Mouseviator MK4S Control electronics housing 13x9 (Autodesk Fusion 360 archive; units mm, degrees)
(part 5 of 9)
sketch "Sketch2" plane through (0, 0, 10) normal (0, 0, 1) x axis (-1, 0, 0)
  line L1 (-46.1449, 57.9621) -> (-21.0144, 57.9621)
  line L2 (-41.1449, 60.9621) -> (-46.1449, 57.9621)
  line L3 (-70.7839, 60.9621) -> (-41.1449, 60.9621)
  line L4 (-65.7839, 57.9621) -> (-70.7839, 60.9621)
  line L5 (-90.9144, 57.9621) -> (-65.7839, 57.9621)
  line L6 (-90.9144, 12.8316) -> (-90.9144, 57.9621)
  line L7 (-93.9144, 17.8316) -> (-90.9144, 12.8316)
  line L8 (-93.9144, -11.8074) -> (-93.9144, 17.8316)
  line L9 (-90.9144, -6.8074) -> (-93.9144, -11.8074)
  line L10 (-90.9144, -51.9379) -> (-90.9144, -6.8074)
  line L11 (-65.7839, -51.9379) -> (-90.9144, -51.9379)
  line L12 (-70.7839, -54.9379) -> (-65.7839, -51.9379)
  line L13 (-41.1449, -54.9379) -> (-70.7839, -54.9379)
  line L14 (-46.1449, -51.9379) -> (-41.1449, -54.9379)
  line L15 (-21.0144, -51.9379) -> (-46.1449, -51.9379)
  line L16 (-21.0144, -6.8074) -> (-21.0144, -51.9379)
  line L17 (-18.0144, -11.8074) -> (-21.0144, -6.8074)
  line L18 (-18.0144, 17.8316) -> (-18.0144, -11.8074)
  line L19 (-21.0144, 12.8316) -> (-18.0144, 17.8316)
  line L20 (-21.0144, 57.9621) -> (-21.0144, 12.8316)
  line L21 (-31.0144, 47.9621) -> (-80.9144, 47.9621)
  line L22 (-31.0144, -41.9379) -> (-31.0144, 47.9621)
  line L23 (-80.9144, -41.9379) -> (-31.0144, -41.9379)
  line L24 (-80.9144, 47.9621) -> (-80.9144, -41.9379)
  line L25 (-86.9644, -32.9879) -> (-24.9644, -32.9879)
  line L26 (-86.9644, 39.0121) -> (-86.9644, -32.9879)
  line L27 (-24.9644, 39.0121) -> (-86.9644, 39.0121)
  line L28 (-24.9644, -32.9879) -> (-24.9644, 39.0121)
  line L29 (-117.1351, 3.0121) -> (55.1062, 3.0121)
  line L30 (-31.0144, -41.9379) -> (-31.0144, 47.9621)
  line L31 (-41.9644, -32.9879) -> (-24.9644, -32.9879)
  line L32 (-41.9644, -12.9879) -> (-41.9644, -32.9879)
  line L33 (-24.9644, -12.9879) -> (-41.9644, -12.9879)
  line L34 (-24.9644, -32.9879) -> (-24.9644, -12.9879)
  line L35 (-55.9644, 85.1837) -> (-55.9644, -169.0595)
  line L36 (-80.9144, -41.9379) -> (-31.0144, -41.9379)
  line L37 (-41.9644, 39.0121) -> (-24.9644, 39.0121)
  line L38 (-41.9644, 19.0121) -> (-41.9644, 39.0121)
  line L39 (-24.9644, 19.0121) -> (-41.9644, 19.0121)
  line L40 (-24.9644, 39.0121) -> (-24.9644, 19.0121)
  line L41 (-69.9644, -32.9879) -> (-86.9644, -32.9879)
  line L42 (-69.9644, -12.9879) -> (-69.9644, -32.9879)
  line L43 (-86.9644, -12.9879) -> (-69.9644, -12.9879)
  line L44 (-86.9644, -32.9879) -> (-86.9644, -12.9879)
  line L45 (-69.9644, 39.0121) -> (-86.9644, 39.0121)
  line L46 (-69.9644, 19.0121) -> (-69.9644, 39.0121)
  line L47 (-86.9644, 39.0121) -> (-86.9644, 19.0121)
  line L48 (-86.9644, 19.0121) -> (-69.9644, 19.0121)
  line L49 (-62.4644, 19.7621) -> (-48.4644, 19.7621)
  line L50 (-62.4644, 28.2621) -> (-48.4644, 28.2621)
  line L51 (-62.4644, -22.2379) -> (-48.4644, -22.2379)
  line L52 (-62.4644, -13.7379) -> (-48.4644, -13.7379)
  line L53 (-80.9144, -35.1088) -> (-31.0144, -35.1088)
  line L54 (-80.9144, -7.9857) -> (-80.9144, -35.1088)
  line L55 (-31.0144, -7.9857) -> (-80.9144, -7.9857)
  line L56 (-31.0144, -35.1088) -> (-31.0144, -7.9857)
  line L57 (-80.9144, 41.133) -> (-31.0144, 41.133)
  line L58 (-80.9144, 14.0099) -> (-80.9144, 41.133)
  line L59 (-31.0144, 14.0099) -> (-80.9144, 14.0099)
  line L60 (-31.0144, 41.133) -> (-31.0144, 14.0099)
  line L61 (-76.712, 3.0121) -> (94.8831, 3.0121)
  circle C1 centre (-35.9644, -21.9879) radius 3.5
  circle C2 centre (-35.9644, 28.0121) radius 3.5
  circle C3 centre (-75.9644, -21.9879) radius 3.5
  circle C4 centre (-75.9644, 28.0121) radius 3.5
  circle C5 centre (-62.4644, 24.0121) radius 1.7
  arc A1 centre (-48.4644, 24.0121) radius 4.25 clockwise from (-48.4644, 28.2621) to (-48.4644, 19.7621)
  arc A2 centre (-62.4644, 24.0121) radius 4.25 clockwise from (-62.4644, 19.7621) to (-62.4644, 28.2621)
  arc A3 centre (-62.4644, -17.9879) radius 4.25 clockwise from (-62.4644, -22.2379) to (-62.4644, -13.7379)
  arc A4 centre (-48.4644, -17.9879) radius 4.25 clockwise from (-48.4644, -13.7379) to (-48.4644, -22.2379)
  circle C6 centre (-62.4644, -17.9879) radius 1.7
  point P30 (-24.9644, -32.9879)
  point P45 (-24.9644, 39.0121)
  point P38 (-41.9644, -32.9879)
  point P46 (-41.9644, 39.0121)
  point P39 (-41.9644, -12.9879)
  point P47 (-41.9644, 19.0121)
  point P40 (-24.9644, -12.9879)
  point P48 (-24.9644, 19.0121)
  point P50 (-86.9644, -32.9879)
  point P51 (-69.9644, -32.9879)
  point P52 (-69.9644, -12.9879)
  point P53 (-86.9644, -12.9879)
  point P55 (-86.9644, 39.0121)
  point P56 (-69.9644, 39.0121)
  point P57 (-69.9644, 19.0121)
  point P58 (-86.9644, 19.0121)
  point P63 (-48.4644, 19.7621)
  point P72 (-48.4644, -13.7379)
  point P64 (-62.4644, 19.7621)
  point P69 (-62.4644, -13.7379)
  point P65 (-48.4644, 28.2621)
  point P70 (-48.4644, -22.2379)
  point P66 (-62.4644, 28.2621)
  point P68 (-62.4644, -22.2379)
  point P76 (-80.9144, -7.9857)
  point P74 (-31.0144, -35.1088)
  point P78 (-31.0144, 41.133)
  point P75 (-80.9144, -35.1088)
  point P79 (-80.9144, 41.133)
  point P80 (-80.9144, 14.0099)
  point P77 (-31.0144, -7.9857)
  point P81 (-31.0144, 14.0099)
  point P31 (-86.9644, -32.9879)
  point P33 (-24.9644, 39.0121)
  point P41 (-35.9644, -21.9879)
  point P60 (-62.4644, 24.0121)
  horizontal L25
  vertical L26
  horizontal L27
  vertical L28
  perpendicular L6 L29
  midpoint L29 L30
  horizontal L31
  vertical L32
  horizontal L33
  vertical L34
  perpendicular L21 L35
  midpoint L35 L36
  symmetric P30 L29 P45
  symmetric L29 P38 P46
  symmetric L29 P39 P47
  symmetric L29 P40 P48
  symmetric L29 C1 C2
  symmetric P30 L35 P50
  symmetric P38 L35 P51
  symmetric P39 L35 P52
  symmetric P40 L35 P53
  symmetric C1 L35 C3
  symmetric L35 P45 P55
  symmetric L35 P46 P56
  symmetric L35 P47 P57
  symmetric L35 P48 P58
  symmetric L35 C2 C4
  concentric C5 A2
  tangent L49 A2
  perpendicular L35 L49
  tangent L50 A2
  perpendicular L35 L50
  symmetric L29 C5 C6
  symmetric L29 P63 P72
  symmetric L29 P64 P69
  symmetric L29 P65 P70
  symmetric L29 P66 P68
  symmetric L29 A1 A4
  symmetric L29 A2 A3
  horizontal L53
  vertical L54
  horizontal L55
  vertical L56
  coincident L24 P76
  coincident L30 P74
  symmetric L29 P74 P78
  symmetric L29 P75 P79
  symmetric L29 P76 P80
  symmetric L29 P77 P81
  dimension "uno_box_width" distance P30 P31 = 62
  dimension "uno_box_height" distance P30 P33 = 72
  dimension "uno_corner_stand_width" distance P30 P38 = 17
  dimension "uno_corner_stand_height" distance P30 P40 = 20
  dimension "uno_box_stand_hole_d" diameter C1 = 7
  dimension "d387" distance L34 P41 = 11
  dimension "d388" distance L25 P41 = 11
  dimension "d389" distance L25 L29 = 36 (= "uno_box_height / 2")
  dimension "d390" distance L26 L35 = 31 (= "uno_box_width / 2")
  dimension "d391" diameter C5 = 3.4 (= "M3_d")
  dimension "d392" distance L26 P60 = 24.5
  dimension "d394" diameter A2 = 8.5 (= "M3_d * 2.5")
  dimension "d395" diameter A1 = 8.5 (= "M3_d * 2.5")
  dimension "d410" distance L52 L61 = 16.75
extrude "Extrude3" add sketch "Sketch2" profile of L22 L24 L30 L31 L32 L33 C1 L37 L38 L39 C2 L41 L42 L43 C3 L45 L46 L48 C4 C5 A2 A1 L49 L50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 no distance stored
extrude "Extrude4" add sketch "Sketch2" profile of L22 L24 L30 L31 L32 L33 L34 C1 L37 L38 L39 L40 C2 L41 L42 L43 L44 C3 L45 L46 L47 L48 C4 C5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 along normal blind 5 (= "el_stand_height")
sketch "Sketch3" plane through (0, 0, 15) normal (0, 0, 1) x axis (-1, 0, 0)
  line L1 (-41.9644, -12.9879) -> (-24.9644, -12.9879)
  line L2 (-41.9644, -32.9879) -> (-41.9644, -12.9879)
  line L3 (-24.9644, -32.9879) -> (-41.9644, -32.9879)
  line L4 (-24.9644, -12.9879) -> (-24.9644, -32.9879)
  circle C1 centre (-75.9644, 28.0121) radius 3.5
  circle C2 centre (-35.9644, 28.0121) radius 3.5
  circle C3 centre (-35.9644, -21.9879) radius 3.5
  circle C4 centre (-75.9644, -21.9879) radius 3.5
  circle C5 centre (-62.4644, -17.9879) radius 1.7
  circle C6 centre (-62.4644, 24.0121) radius 1.7
hole "Hole1" HoleDepth 7.5 (= "( plate_thick + el_stand_height ) * 0.75") HoleDiameter 2.4 TipAngle 118
extrude "Extrude5" cut sketch "Sketch3" profile of C1 C2 C3 C4 against normal blind 0.5
fillet "Fillet1" radius 1.25 (= "el_stand_height * 0.25")
fillet "Fillet2" radius 1.25 (= "el_stand_height * 0.25")
sketch "Sketch1" plane through (0, 0, 5) normal (0, 0, 1) x axis (-1, 0, 0)
  line L1 (-98.9644, -53.9879) -> (-98.9644, -59.9879)
  line L2 (-92.9644, -53.9879) -> (-98.9644, -53.9879)
  line L3 (-92.9644, -59.9879) -> (-92.9644, -53.9879)
  line L4 (-98.9644, -59.9879) -> (-92.9644, -59.9879)
  line L5 (-98.9644, 60.0121) -> (-92.9644, 60.0121)
  line L6 (-98.9644, 66.0121) -> (-98.9644, 60.0121)
  line L7 (-92.9644, 66.0121) -> (-98.9644, 66.0121)
  line L8 (-92.9644, 60.0121) -> (-92.9644, 66.0121)
  line L9 (-12.9644, 60.0121) -> (-12.9644, 66.0121)
  line L10 (-18.9644, 60.0121) -> (-12.9644, 60.0121)
  line L11 (-18.9644, 66.0121) -> (-18.9644, 60.0121)
  line L12 (-12.9644, 66.0121) -> (-18.9644, 66.0121)
  line L13 (-12.9644, -53.9879) -> (-18.9644, -53.9879)
  line L14 (-12.9644, -59.9879) -> (-12.9644, -53.9879)
  line L15 (-18.9644, -59.9879) -> (-12.9644, -59.9879)
  line L16 (-18.9644, -53.9879) -> (-18.9644, -59.9879)
  line L17 (-45.9644, -51.9879) -> (-20.9644, -51.9879)
  line L18 (-40.9644, -54.9879) -> (-45.9644, -51.9879)
  line L19 (-70.9644, -54.9879) -> (-40.9644, -54.9879)
  line L20 (-65.9644, -51.9879) -> (-70.9644, -54.9879)
  line L21 (-90.9644, -51.9879) -> (-65.9644, -51.9879)
  line L22 (-90.9644, -6.9879) -> (-90.9644, -51.9879)
  line L23 (-93.9644, -11.9879) -> (-90.9644, -6.9879)
  line L24 (-93.9644, 18.0121) -> (-93.9644, -11.9879)
  line L25 (-90.9644, 13.0121) -> (-93.9644, 18.0121)
  line L26 (-90.9644, 58.0121) -> (-90.9644, 13.0121)
  line L27 (-65.9644, 58.0121) -> (-90.9644, 58.0121)
  line L28 (-70.9644, 61.0121) -> (-65.9644, 58.0121)
  line L29 (-40.9644, 61.0121) -> (-70.9644, 61.0121)
  line L30 (-45.9644, 58.0121) -> (-40.9644, 61.0121)
  line L31 (-20.9644, 58.0121) -> (-45.9644, 58.0121)
  line L32 (-20.9644, 13.0121) -> (-20.9644, 58.0121)
  line L33 (-17.9644, 18.0121) -> (-20.9644, 13.0121)
  line L34 (-17.9644, -11.9879) -> (-17.9644, 18.0121)
  line L35 (-20.9644, -6.9879) -> (-17.9644, -11.9879)
  line L36 (-20.9644, -51.9879) -> (-20.9644, -6.9879)
  line L37 (-10.9644, -6.9879) -> (-10.9644, -61.9879)
  line L38 (-13.9644, -11.9879) -> (-10.9644, -6.9879)
  line L39 (-13.9644, 18.0121) -> (-13.9644, -11.9879)
  line L40 (-10.9644, 13.0121) -> (-13.9644, 18.0121)
  line L41 (-10.9644, 68.0121) -> (-10.9644, 13.0121)
  line L42 (-45.9644, 68.0121) -> (-10.9644, 68.0121)
  line L43 (-40.9644, 65.0121) -> (-45.9644, 68.0121)
  line L44 (-70.9644, 65.0121) -> (-40.9644, 65.0121)
  line L45 (-65.9644, 68.0121) -> (-70.9644, 65.0121)
  line L46 (-100.9644, 68.0121) -> (-65.9644, 68.0121)
  line L47 (-100.9644, 13.0121) -> (-100.9644, 68.0121)
  line L48 (-97.9644, 18.0121) -> (-100.9644, 13.0121)
  line L49 (-97.9644, -11.9879) -> (-97.9644, 18.0121)
  line L50 (-100.9644, -6.9879) -> (-97.9644, -11.9879)
  line L51 (-100.9644, -61.9879) -> (-100.9644, -6.9879)
  line L52 (-65.9644, -61.9879) -> (-100.9644, -61.9879)
  line L53 (-70.9644, -58.9879) -> (-65.9644, -61.9879)
  line L54 (-40.9644, -58.9879) -> (-70.9644, -58.9879)
  line L55 (-45.9644, -61.9879) -> (-40.9644, -58.9879)
  line L56 (-10.9644, -61.9879) -> (-45.9644, -61.9879)
  line L57 (-45.9644, -51.9879) -> (-20.9644, -51.9879)
  line L58 (-40.9644, -54.9879) -> (-55.9644, -54.9879)
  line L59 (-40.9644, -54.9879) -> (-45.9644, -51.9879)
  line L60 (-65.9644, -51.9879) -> (-70.9644, -54.9879)
  line L61 (-70.9644, -54.9879) -> (-55.9644, -54.9879)
  line L62 (-65.9644, -51.9879) -> (-90.9644, -51.9879)
  line L63 (-90.9644, -6.9879) -> (-90.9644, -51.9879)
  line L64 (-93.9644, -11.9879) -> (-93.9644, 3.0121)
  line L65 (-93.9644, -11.9879) -> (-90.9644, -6.9879)
  line L66 (-93.9644, 18.0121) -> (-90.9644, 13.0121)
  line L67 (-93.9644, 18.0121) -> (-93.9644, 3.0121)
  line L68 (-90.9644, 58.0121) -> (-90.9644, 13.0121)
  line L69 (-65.9644, 58.0121) -> (-90.9644, 58.0121)
  line L70 (-40.9644, 61.0121) -> (-45.9644, 58.0121)
  line L71 (-40.9644, 61.0121) -> (-55.9644, 61.0121)
  line L72 (-70.9644, 61.0121) -> (-55.9644, 61.0121)
  line L73 (-65.9644, 58.0121) -> (-70.9644, 61.0121)
  line L74 (-45.9644, 58.0121) -> (-20.9644, 58.0121)
  line L75 (-20.9644, 13.0121) -> (-20.9644, 58.0121)
  line L76 (-17.9644, 18.0121) -> (-17.9644, 3.0121)
  line L77 (-17.9644, -11.9879) -> (-17.9644, 3.0121)
  line L78 (-17.9644, -11.9879) -> (-20.9644, -6.9879)
  line L79 (-17.9644, 18.0121) -> (-20.9644, 13.0121)
  line L80 (-20.9644, -6.9879) -> (-20.9644, -51.9879)
  line L81 (-65.7839, -51.9379) -> (-70.7839, -54.9379)
  line L82 (-90.9144, -51.9379) -> (-65.7839, -51.9379)
  line L83 (-90.9144, -6.8074) -> (-90.9144, -51.9379)
  line L84 (-93.9144, -11.8074) -> (-90.9144, -6.8074)
  line L85 (-93.9144, 17.8316) -> (-93.9144, -11.8074)
  line L86 (-90.9144, 12.8316) -> (-93.9144, 17.8316)
  line L87 (-90.9144, 57.9621) -> (-90.9144, 12.8316)
  line L88 (-65.7839, 57.9621) -> (-90.9144, 57.9621)
  line L89 (-70.7839, 60.9621) -> (-65.7839, 57.9621)
  line L90 (-41.1449, 60.9621) -> (-70.7839, 60.9621)
  line L91 (-46.1449, 57.9621) -> (-41.1449, 60.9621)
  line L92 (-21.0144, 57.9621) -> (-46.1449, 57.9621)
  line L93 (-21.0144, 12.8316) -> (-21.0144, 57.9621)
  line L94 (-18.0144, 17.8316) -> (-21.0144, 12.8316)
  line L95 (-18.0144, -11.8074) -> (-18.0144, 17.8316)
  line L96 (-21.0144, -6.8074) -> (-18.0144, -11.8074)
  line L97 (-21.0144, -51.9379) -> (-21.0144, -6.8074)
  line L98 (-46.1449, -51.9379) -> (-21.0144, -51.9379)
  line L99 (-41.1449, -54.9379) -> (-46.1449, -51.9379)
  line L100 (-70.7839, -54.9379) -> (-41.1449, -54.9379)
  line L101 (-90.9144, 12.8316) -> (-90.9144, -6.8074)
  line L102 (-46.1449, -51.9379) -> (-65.7839, -51.9379)
  line L103 (-21.0144, 12.8316) -> (-21.0144, -6.8074)
  line L104 (-65.7839, 57.9621) -> (-46.1449, 57.9621)
  line L105 (-80.9144, -41.9379) -> (-31.0144, -41.9379)
  line L106 (-80.9144, 47.9621) -> (-80.9144, -41.9379)
  line L107 (-31.0144, 47.9621) -> (-80.9144, 47.9621)
  line L108 (-31.0144, -41.9379) -> (-31.0144, 47.9621)
  circle C1 centre (-24.4644, 61.5121) radius 1.7
  circle C2 centre (-93.9644, 54.5121) radius 1.7
  circle C3 centre (-87.4644, -55.4879) radius 1.7
  circle C4 centre (-17.4644, -48.4879) radius 1.7
  circle C5 centre (-24.4644, -55.4879) radius 1.7
  circle C6 centre (-93.9644, -48.4879) radius 1.7
  circle C7 centre (-87.4644, 61.5121) radius 1.7
  circle C8 centre (-17.4644, 54.5121) radius 1.7
  circle C9 centre (-60.9644, -53.4879) radius 0.75
  circle C10 centre (-50.9644, -53.4879) radius 0.75
  circle C11 centre (-92.4644, -1.9879) radius 0.75
  circle C12 centre (-92.4644, 8.0121) radius 0.75
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  horizontal L105
  vertical L106
  horizontal L107
  vertical L108
  dimension "d279_3" = 0.05 (= "wall_clearance")
  dimension "d289_3" distance L82 L105 = 10 (= "plate_square_thick")
  dimension "d290_3" distance L83 L106 = 10 (= "plate_square_thick")
  dimension "d291_3" distance L97 L108 = 10 (= "plate_square_thick")
  dimension "d292_3" distance L88 L107 = 10 (= "plate_square_thick")
extrude "Extrude1" new body sketch "Sketch1" along normal blind 5 (= "plate_thick") named "d293_3"
extrude "Extrude2" add sketch "Sketch1" blind -2.45 (= "-( plate_thick / 2 ) + wall_clearance") named "d296_3" from offset 5 (= "plate_thick") named "d295_3"
position "Position15"
sketch "wago bays" plane through (0, 0, 10) normal (0, 0, 1) x axis (-1, 0, 0)
  line L1 (-46.1449, 57.9621) -> (-21.0144, 57.9621)
  line L2 (-41.1449, 60.9621) -> (-46.1449, 57.9621)
  line L3 (-70.7839, 60.9621) -> (-41.1449, 60.9621)
  line L4 (-65.7839, 57.9621) -> (-70.7839, 60.9621)
  line L5 (-90.9144, 57.9621) -> (-65.7839, 57.9621)
  line L6 (-90.9144, 12.8316) -> (-90.9144, 57.9621)
  line L7 (-93.9144, 17.8316) -> (-90.9144, 12.8316)
  line L8 (-93.9144, -11.8074) -> (-93.9144, 17.8316)
  line L9 (-90.9144, -6.8074) -> (-93.9144, -11.8074)
  line L10 (-90.9144, -51.9379) -> (-90.9144, -6.8074)
  line L11 (-65.7839, -51.9379) -> (-90.9144, -51.9379)
  line L12 (-70.7839, -54.9379) -> (-65.7839, -51.9379)
  line L13 (-41.1449, -54.9379) -> (-70.7839, -54.9379)
  line L14 (-46.1449, -51.9379) -> (-41.1449, -54.9379)
  line L15 (-21.0144, -51.9379) -> (-46.1449, -51.9379)
  line L16 (-21.0144, -6.8074) -> (-21.0144, -51.9379)
  line L17 (-18.0144, -11.8074) -> (-21.0144, -6.8074)
  line L18 (-18.0144, 17.8316) -> (-18.0144, -11.8074)
  line L19 (-21.0144, 12.8316) -> (-18.0144, 17.8316)
  line L20 (-21.0144, 57.9621) -> (-21.0144, 12.8316)
  line L21 (-31.0144, 47.9621) -> (-80.9144, 47.9621)
  line L22 (-31.0144, -41.9379) -> (-31.0144, 47.9621)
  line L23 (-80.9144, -41.9379) -> (-31.0144, -41.9379)
  line L24 (-80.9144, 47.9621) -> (-80.9144, -41.9379)
  line L25 (-23.9487, 49.8139) -> (-23.9644, 37.8139)
  line L26 (-87.9644, 49.8113) -> (-23.9487, 49.8139)
  line L27 (-87.9644, 37.8123) -> (-87.9644, 49.8113)
  line L28 (-23.9644, 37.8139) -> (-87.9644, 37.8123)
  line L29 (-25.9618, 39.8139) -> (-85.9644, 39.8123)
  line L30 (-25.9513, 47.8138) -> (-25.9618, 39.8139)
  line L31 (-85.9644, 47.8114) -> (-25.9513, 47.8138)
  line L32 (-85.9644, 39.8123) -> (-85.9644, 47.8114)
  line L33 (-90.9144, 57.9621) -> (-90.9144, 12.8316)
  line L34 (-87.9638, 25.8133) -> (-23.9481, 25.8139)
  line L35 (-87.9644, 37.8123) -> (-87.9638, 25.8133)
  line L36 (-23.9644, 37.8139) -> (-87.9644, 37.8123)
  line L37 (-23.9481, 25.8139) -> (-23.9644, 37.8139)
  line L38 (-85.9639, 27.8133) -> (-25.9508, 27.8139)
  line L39 (-85.9643, 35.8123) -> (-85.9639, 27.8133)
  line L40 (-25.9508, 27.8139) -> (-25.9617, 35.8139)
  line L41 (-25.9617, 35.8139) -> (-85.9643, 35.8123)
  line L42 (-85.9639, -1.6867) -> (-25.9508, -1.6861)
  line L43 (-85.9643, 6.3123) -> (-85.9639, -1.6867)
  line L44 (-25.9617, 6.3139) -> (-85.9643, 6.3123)
  line L45 (-25.9508, -1.6861) -> (-25.9617, 6.3139)
  line L46 (-23.9644, 8.3139) -> (-87.9644, 8.3123)
  line L47 (-23.9481, -3.6861) -> (-23.9644, 8.3139)
  line L48 (-87.9644, 8.3123) -> (-87.9638, -3.6867)
  line L49 (-87.9638, -3.6867) -> (-23.9481, -3.6861)
  line L50 (-25.9617, -33.6861) -> (-85.9643, -33.6877)
  line L51 (-25.9508, -41.6861) -> (-25.9617, -33.6861)
  line L52 (-85.9639, -41.6867) -> (-25.9508, -41.6861)
  line L53 (-85.9643, -33.6877) -> (-85.9639, -41.6867)
  line L54 (-23.9644, -31.6861) -> (-87.9644, -31.6877)
  line L55 (-23.9481, -43.6861) -> (-23.9644, -31.6861)
  line L56 (-87.9644, -31.6877) -> (-87.9638, -43.6867)
  line L57 (-87.9638, -43.6867) -> (-23.9481, -43.6861)
  line L58 (-90.9644, -51.9379) -> (-21.0144, -51.9379)
  line L59 (-90.9644, 58.0121) -> (-90.9644, -51.9379)
  line L60 (-21.0144, 58.0121) -> (-90.9644, 58.0121)
  line L61 (-21.0144, -51.9379) -> (-21.0144, 58.0121)
  line L62 (-159.1501, 3.0121) -> (-2.6788, 3.0121)
  line L63 (-55.9644, 72.2473) -> (-55.9644, -156.1231)
  line L64 (-80.9144, 47.9621) -> (-80.9144, -41.9379)
  line L65 (-80.9144, -41.9379) -> (-31.0144, -41.9379)
  point P30 (-23.9644, 37.8139)
  point P43 (-23.9644, 37.8139)
  point P31 (-23.9487, 49.8139)
  point P40 (-23.9481, 25.8139)
  point P32 (-87.9644, 49.8113)
  point P41 (-87.9638, 25.8133)
  point P33 (-87.9644, 37.8123)
  point P42 (-87.9644, 37.8123)
  point P34 (-85.9644, 39.8123)
  point P46 (-85.9643, 35.8123)
  point P35 (-25.9618, 39.8139)
  point P47 (-25.9617, 35.8139)
  point P36 (-25.9513, 47.8138)
  point P44 (-25.9508, 27.8139)
  point P37 (-85.9644, 47.8114)
  point P45 (-85.9639, 27.8133)
  point P29 (-90.9644, 58.0121)
  point P66 (-90.9644, 58.0121)
  point P17 (-21.0144, -51.9379)
  point P64 (-21.0144, -51.9379)
  symmetric P30 L28 P43
  symmetric P31 L28 P40
  symmetric P32 L28 P41
  symmetric P33 L28 P42
  symmetric L28 P34 P46
  symmetric L28 P35 P47
  symmetric L28 P36 P44
  symmetric L28 P37 P45
  horizontal L58
  vertical L59
  horizontal L60
  vertical L61
  coincident P29 P66
  coincident P17 P64
  perpendicular L24 L62
  vertical L63
  midpoint L62 L64
  midpoint L63 L65
  dimension "d419" distance P30 P31 = 12 (= "wago_box_height")
  dimension "d420" distance P30 P33 = 64 (= "wago10_box_width")
  dimension "d424" distance L27 L59 = 3
sketch "supports" plane through (0, 0, 10) normal (0, 0, 1) x axis (-1, 0, 0)
  line L1 (-80.9144, 47.9621) -> (-80.9144, -41.9379)
  line L2 (-31.0144, 47.9621) -> (-80.9144, 47.9621)
  line L3 (-31.0144, -41.9379) -> (-31.0144, 47.9621)
  line L4 (-80.9144, -41.9379) -> (-31.0144, -41.9379)
  line L5 (-59.9644, -41.9379) -> (-51.9644, -41.9379)
  line L6 (-59.9644, 47.9621) -> (-59.9644, -41.9379)
  line L7 (-51.9644, 47.9621) -> (-59.9644, 47.9621)
  line L8 (-51.9644, -41.9379) -> (-51.9644, 47.9621)
  line L9 (-74.9644, 47.9621) -> (-74.9644, -41.9379)
  line L10 (-66.9644, 47.9621) -> (-74.9644, 47.9621)
  line L11 (-66.9644, -41.9379) -> (-66.9644, 47.9621)
  line L12 (-74.9644, -41.9379) -> (-66.9644, -41.9379)
  line L13 (-36.9644, -41.9379) -> (-36.9644, 47.9621)
  line L14 (-44.9644, -41.9379) -> (-36.9644, -41.9379)
  line L15 (-44.9644, 47.9621) -> (-44.9644, -41.9379)
  line L16 (-36.9644, 47.9621) -> (-44.9644, 47.9621)
  line L17 (-55.9644, 72.2473) -> (-55.9644, -156.1231)
  line L18 (-74.9782, -1.681) -> (-36.9644, -1.681)
  line L19 (-74.9782, -11.681) -> (-74.9782, -1.681)
  line L20 (-36.9644, -11.681) -> (-74.9782, -11.681)
  line L21 (-36.9644, -1.681) -> (-36.9644, -11.681)
  line L22 (-74.9782, 27.819) -> (-36.9644, 27.819)
  line L23 (-74.9782, 17.819) -> (-74.9782, 27.819)
  line L24 (-36.9644, 17.819) -> (-74.9782, 17.819)
  line L25 (-36.9644, 27.819) -> (-36.9644, 17.819)
  line L26 (-74.9782, -23.681) -> (-36.9644, -23.681)
  line L27 (-74.9782, -33.681) -> (-74.9782, -23.681)
  line L28 (-36.9644, -33.681) -> (-74.9782, -33.681)
  line L29 (-36.9644, -23.681) -> (-36.9644, -33.681)
  point P8 (-59.9644, 47.9621)
  point P6 (-51.9644, -41.9379)
  point P20 (-36.9644, -1.681)
  point P7 (-59.9644, -41.9379)
  point P10 (-66.9644, -41.9379)
  point P12 (-74.9644, -41.9379)
  point P14 (-36.9644, -41.9379)
  point P16 (-44.9644, -41.9379)
  point P23 (-36.9644, -11.681)
  point P25 (-36.9644, 27.819)
  point P27 (-36.9644, 17.819)
  point P29 (-36.9644, -23.681)
  point P31 (-36.9644, -33.681)
  horizontal L5
  vertical L6
  horizontal L7
  vertical L8
  coincident L2 P8
  coincident L4 P6
  horizontal L12
  vertical L9
  horizontal L10
  vertical L11
  horizontal L14
  vertical L15
  horizontal L16
  vertical L13
  midpoint L5 L17
  horizontal L18
  vertical L19
  horizontal L20
  vertical L21
  coincident L13 P20
  horizontal L22
  vertical L23
  horizontal L24
  vertical L25
  horizontal L26
  vertical L27
  horizontal L28
  vertical L29
  dimension "d428" distance P6 P7 = 8 (= "base_vertical_support_width")
  dimension "d429" distance P10 P12 = 8 (= "base_vertical_support_width")
  dimension "d430" distance P14 P16 = 8 (= "base_vertical_support_width")
  dimension "base_vertical_support_spacing" distance L8 L15 = 7
  dimension "d432" distance L6 L11 = 7 (= "base_vertical_support_spacing")
  dimension "base_text_plate_height" distance P20 P23 = 10
  dimension "d434" distance P25 P27 = 10
  dimension "d435" distance P29 P31 = 10
extrude "Extrude3" add sketch "supports" profile of L2 L4 L5 L6 L7 L8 L9 L10 L11 L12 L13 L14 L15 L16 L17 L18 L20 L21 L22 L24 L25 L26 L28 L29 no distance stored
extrude "Extrude4" add sketch "supports" profile of L6 L8 L11 L15 L18 L20 L22 L24 L26 L28 against normal blind 2.5 (magnitude of "-plate_thick * 0.5")
extrude "Extrude5" add sketch "wago bays" profile of L21 L22 L23 L24 L25 L26 L27 L28 L31 L29 L30 L32 L34 L35 L36 L37 L38 L39 L40 L41 L42 L43 L44 L45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 along normal blind 12 (= "wago_box_height")
sketch "text" plane through (0, 0, 10) normal (0, 0, 1) x axis (-1, 0, 0)
  line L1 (-46.1449, 57.9621) -> (-21.0144, 57.9621)
  line L2 (-41.1449, 60.9621) -> (-46.1449, 57.9621)
  line L3 (-70.7839, 60.9621) -> (-41.1449, 60.9621)
  line L4 (-65.7839, 57.9621) -> (-70.7839, 60.9621)
  line L5 (-90.9144, 57.9621) -> (-65.7839, 57.9621)
  line L6 (-90.9144, 12.8316) -> (-90.9144, 57.9621)
  line L7 (-93.9144, 17.8316) -> (-90.9144, 12.8316)
  line L8 (-93.9144, -11.8074) -> (-93.9144, 17.8316)
  line L9 (-90.9144, -6.8074) -> (-93.9144, -11.8074)
  line L10 (-90.9144, -51.9379) -> (-90.9144, -6.8074)
  line L11 (-65.7839, -51.9379) -> (-90.9144, -51.9379)
  line L12 (-70.7839, -54.9379) -> (-65.7839, -51.9379)
  line L13 (-41.1449, -54.9379) -> (-70.7839, -54.9379)
  line L14 (-46.1449, -51.9379) -> (-41.1449, -54.9379)
  line L15 (-21.0144, -51.9379) -> (-46.1449, -51.9379)
  line L16 (-21.0144, -6.8074) -> (-21.0144, -51.9379)
  line L17 (-18.0144, -11.8074) -> (-21.0144, -6.8074)
  line L18 (-18.0144, 17.8316) -> (-18.0144, -11.8074)
  line L19 (-21.0144, 12.8316) -> (-18.0144, 17.8316)
  line L20 (-21.0144, 57.9621) -> (-21.0144, 12.8316)
  line L21 (-80.9144, -31.6875) -> (-87.9644, -31.6877)
  line L22 (-80.9144, -3.6866) -> (-80.9144, -31.6875)
  line L23 (-87.9638, -3.6867) -> (-80.9144, -3.6866)
  line L24 (-87.9644, 8.3123) -> (-87.9638, -3.6867)
  line L25 (-80.9144, 8.3125) -> (-87.9644, 8.3123)
  line L26 (-80.9144, 25.8134) -> (-80.9144, 8.3125)
  line L27 (-87.9638, 25.8133) -> (-80.9144, 25.8134)
  line L28 (-87.9644, 37.8123) -> (-87.9638, 25.8133)
  line L29 (-87.9644, 49.8113) -> (-87.9644, 37.8123)
  line L30 (-23.9487, 49.8139) -> (-87.9644, 49.8113)
  line L31 (-23.9644, 37.8139) -> (-23.9487, 49.8139)
  line L32 (-23.9481, 25.8139) -> (-23.9644, 37.8139)
  line L33 (-31.0144, 25.8139) -> (-23.9481, 25.8139)
  line L34 (-31.0144, 8.3138) -> (-31.0144, 25.8139)
  line L35 (-23.9644, 8.3139) -> (-31.0144, 8.3138)
  line L36 (-23.9481, -3.6861) -> (-23.9644, 8.3139)
  line L37 (-31.0144, -3.6861) -> (-23.9481, -3.6861)
  line L38 (-31.0144, -31.6862) -> (-31.0144, -3.6861)
  line L39 (-23.9644, -31.6861) -> (-31.0144, -31.6862)
  line L40 (-23.9481, -43.6861) -> (-23.9644, -31.6861)
  line L41 (-87.9638, -43.6867) -> (-23.9481, -43.6861)
  line L42 (-87.9644, -31.6877) -> (-87.9638, -43.6867)
  curve K1
  curve K2
  curve K3
  curve K4
  curve K5
  curve K6
  curve K7
  curve K8
  curve K9
  curve K10
  curve K11
  curve K12
  line L43 (-55.9644, 24.81) -> (-55.9644, -134.6858)
  vertical L43
  midpoint L13 L43
  coincident L43
  coincident L43
  coincident L43
  dimension "d442" Text1-Height = 5
  dimension "d443" Text2-Height = 5
  dimension "d444" Text3-Height = 5
emboss "Emboss1" sketch "text" Depth 1 named "text_emboss" Horizontal Distance 0 Vertical Distance 0 Rotation Angle 0
emboss "Emboss2" sketch "text" Depth 1 (= "text_emboss") Horizontal Distance 0 Vertical Distance 0 Rotation Angle 0
sketch "Sketch1" plane through (0, 0, 5) normal (0, 0, 1) x axis (-1, 0, 0)
  line L1 (-98.9644, -53.9879) -> (-98.9644, -59.9879)
  line L2 (-92.9644, -53.9879) -> (-98.9644, -53.9879)
  line L3 (-92.9644, -59.9879) -> (-92.9644, -53.9879)
  line L4 (-98.9644, -59.9879) -> (-92.9644, -59.9879)
  line L5 (-98.9644, 60.0121) -> (-92.9644, 60.0121)
  line L6 (-98.9644, 66.0121) -> (-98.9644, 60.0121)
  line L7 (-92.9644, 66.0121) -> (-98.9644, 66.0121)
  line L8 (-92.9644, 60.0121) -> (-92.9644, 66.0121)
  line L9 (-12.9644, 60.0121) -> (-12.9644, 66.0121)
  line L10 (-18.9644, 60.0121) -> (-12.9644, 60.0121)
  line L11 (-18.9644, 66.0121) -> (-18.9644, 60.0121)
  line L12 (-12.9644, 66.0121) -> (-18.9644, 66.0121)
  line L13 (-12.9644, -53.9879) -> (-18.9644, -53.9879)
  line L14 (-12.9644, -59.9879) -> (-12.9644, -53.9879)
  line L15 (-18.9644, -59.9879) -> (-12.9644, -59.9879)
  line L16 (-18.9644, -53.9879) -> (-18.9644, -59.9879)
  line L17 (-45.9644, -51.9879) -> (-20.9644, -51.9879)
  line L18 (-40.9644, -54.9879) -> (-45.9644, -51.9879)
  line L19 (-70.9644, -54.9879) -> (-40.9644, -54.9879)
  line L20 (-65.9644, -51.9879) -> (-70.9644, -54.9879)
  line L21 (-90.9644, -51.9879) -> (-65.9644, -51.9879)
  line L22 (-90.9644, -6.9879) -> (-90.9644, -51.9879)
  line L23 (-93.9644, -11.9879) -> (-90.9644, -6.9879)
  line L24 (-93.9644, 18.0121) -> (-93.9644, -11.9879)
  line L25 (-90.9644, 13.0121) -> (-93.9644, 18.0121)
  line L26 (-90.9644, 58.0121) -> (-90.9644, 13.0121)
  line L27 (-65.9644, 58.0121) -> (-90.9644, 58.0121)
  line L28 (-70.9644, 61.0121) -> (-65.9644, 58.0121)
  line L29 (-40.9644, 61.0121) -> (-70.9644, 61.0121)
  line L30 (-45.9644, 58.0121) -> (-40.9644, 61.0121)
  line L31 (-20.9644, 58.0121) -> (-45.9644, 58.0121)
  line L32 (-20.9644, 13.0121) -> (-20.9644, 58.0121)
  line L33 (-17.9644, 18.0121) -> (-20.9644, 13.0121)
  line L34 (-17.9644, -11.9879) -> (-17.9644, 18.0121)
  line L35 (-20.9644, -6.9879) -> (-17.9644, -11.9879)
  line L36 (-20.9644, -51.9879) -> (-20.9644, -6.9879)
  line L37 (-10.9644, -6.9879) -> (-10.9644, -61.9879)
  line L38 (-13.9644, -11.9879) -> (-10.9644, -6.9879)
  line L39 (-13.9644, 18.0121) -> (-13.9644, -11.9879)
  line L40 (-10.9644, 13.0121) -> (-13.9644, 18.0121)
  line L41 (-10.9644, 68.0121) -> (-10.9644, 13.0121)
  line L42 (-45.9644, 68.0121) -> (-10.9644, 68.0121)
  line L43 (-40.9644, 65.0121) -> (-45.9644, 68.0121)
  line L44 (-70.9644, 65.0121) -> (-40.9644, 65.0121)
  line L45 (-65.9644, 68.0121) -> (-70.9644, 65.0121)
  line L46 (-100.9644, 68.0121) -> (-65.9644, 68.0121)
  line L47 (-100.9644, 13.0121) -> (-100.9644, 68.0121)
  line L48 (-97.9644, 18.0121) -> (-100.9644, 13.0121)
  line L49 (-97.9644, -11.9879) -> (-97.9644, 18.0121)
  line L50 (-100.9644, -6.9879) -> (-97.9644, -11.9879)
  line L51 (-100.9644, -61.9879) -> (-100.9644, -6.9879)
  line L52 (-65.9644, -61.9879) -> (-100.9644, -61.9879)
  line L53 (-70.9644, -58.9879) -> (-65.9644, -61.9879)
  line L54 (-40.9644, -58.9879) -> (-70.9644, -58.9879)
  line L55 (-45.9644, -61.9879) -> (-40.9644, -58.9879)
  line L56 (-10.9644, -61.9879) -> (-45.9644, -61.9879)
  line L57 (-45.9644, -51.9879) -> (-20.9644, -51.9879)
  line L58 (-40.9644, -54.9879) -> (-55.9644, -54.9879)
  line L59 (-40.9644, -54.9879) -> (-45.9644, -51.9879)
  line L60 (-65.9644, -51.9879) -> (-70.9644, -54.9879)
  line L61 (-70.9644, -54.9879) -> (-55.9644, -54.9879)
  line L62 (-65.9644, -51.9879) -> (-90.9644, -51.9879)
  line L63 (-90.9644, -6.9879) -> (-90.9644, -51.9879)
  line L64 (-93.9644, -11.9879) -> (-93.9644, 3.0121)
  line L65 (-93.9644, -11.9879) -> (-90.9644, -6.9879)
  line L66 (-93.9644, 18.0121) -> (-90.9644, 13.0121)
  line L67 (-93.9644, 18.0121) -> (-93.9644, 3.0121)
  line L68 (-90.9644, 58.0121) -> (-90.9644, 13.0121)
  line L69 (-65.9644, 58.0121) -> (-90.9644, 58.0121)
  line L70 (-40.9644, 61.0121) -> (-45.9644, 58.0121)
  line L71 (-40.9644, 61.0121) -> (-55.9644, 61.0121)
  line L72 (-70.9644, 61.0121) -> (-55.9644, 61.0121)
  line L73 (-65.9644, 58.0121) -> (-70.9644, 61.0121)
  line L74 (-45.9644, 58.0121) -> (-20.9644, 58.0121)
  line L75 (-20.9644, 13.0121) -> (-20.9644, 58.0121)
  line L76 (-17.9644, 18.0121) -> (-17.9644, 3.0121)
  line L77 (-17.9644, -11.9879) -> (-17.9644, 3.0121)
  line L78 (-17.9644, -11.9879) -> (-20.9644, -6.9879)
  line L79 (-17.9644, 18.0121) -> (-20.9644, 13.0121)
  line L80 (-20.9644, -6.9879) -> (-20.9644, -51.9879)
  line L81 (-65.7839, -51.9379) -> (-70.7839, -54.9379)
  line L82 (-90.9144, -51.9379) -> (-65.7839, -51.9379)
  line L83 (-90.9144, -6.8074) -> (-90.9144, -51.9379)
  line L84 (-93.9144, -11.8074) -> (-90.9144, -6.8074)
  line L85 (-93.9144, 17.8316) -> (-93.9144, -11.8074)
  line L86 (-90.9144, 12.8316) -> (-93.9144, 17.8316)
  line L87 (-90.9144, 57.9621) -> (-90.9144, 12.8316)
  line L88 (-65.7839, 57.9621) -> (-90.9144, 57.9621)
  line L89 (-70.7839, 60.9621) -> (-65.7839, 57.9621)
  line L90 (-41.1449, 60.9621) -> (-70.7839, 60.9621)
  line L91 (-46.1449, 57.9621) -> (-41.1449, 60.9621)
  line L92 (-21.0144, 57.9621) -> (-46.1449, 57.9621)
  line L93 (-21.0144, 12.8316) -> (-21.0144, 57.9621)
  line L94 (-18.0144, 17.8316) -> (-21.0144, 12.8316)
  line L95 (-18.0144, -11.8074) -> (-18.0144, 17.8316)
  line L96 (-21.0144, -6.8074) -> (-18.0144, -11.8074)
  line L97 (-21.0144, -51.9379) -> (-21.0144, -6.8074)
  line L98 (-46.1449, -51.9379) -> (-21.0144, -51.9379)
  line L99 (-41.1449, -54.9379) -> (-46.1449, -51.9379)
  line L100 (-70.7839, -54.9379) -> (-41.1449, -54.9379)
  line L101 (-90.9144, 12.8316) -> (-90.9144, -6.8074)
  line L102 (-46.1449, -51.9379) -> (-65.7839, -51.9379)
  line L103 (-21.0144, 12.8316) -> (-21.0144, -6.8074)
  line L104 (-65.7839, 57.9621) -> (-46.1449, 57.9621)
  line L105 (-80.9144, -41.9379) -> (-31.0144, -41.9379)
  line L106 (-80.9144, 47.9621) -> (-80.9144, -41.9379)
  line L107 (-31.0144, 47.9621) -> (-80.9144, 47.9621)
  line L108 (-31.0144, -41.9379) -> (-31.0144, 47.9621)
  circle C1 centre (-24.4644, 61.5121) radius 1.7
  circle C2 centre (-93.9644, 54.5121) radius 1.7
  circle C3 centre (-87.4644, -55.4879) radius 1.7
  circle C4 centre (-17.4644, -48.4879) radius 1.7
  circle C5 centre (-24.4644, -55.4879) radius 1.7
  circle C6 centre (-93.9644, -48.4879) radius 1.7
  circle C7 centre (-87.4644, 61.5121) radius 1.7
  circle C8 centre (-17.4644, 54.5121) radius 1.7
  circle C9 centre (-60.9644, -53.4879) radius 0.75
  circle C10 centre (-50.9644, -53.4879) radius 0.75
  circle C11 centre (-92.4644, -1.9879) radius 0.75
  circle C12 centre (-92.4644, 8.0121) radius 0.75
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  horizontal L105
  vertical L106
  horizontal L107
  vertical L108
  dimension "d279_4" = 0.05 (= "wall_clearance")
  dimension "d289_4" distance L82 L105 = 10 (= "plate_square_thick")
  dimension "d290_4" distance L83 L106 = 10 (= "plate_square_thick")
  dimension "d291_4" distance L97 L108 = 10 (= "plate_square_thick")
  dimension "d292_4" distance L88 L107 = 10 (= "plate_square_thick")
extrude "Extrude1" new body sketch "Sketch1" along normal blind 5 (= "plate_thick") named "d293_4"
extrude "Extrude2" add sketch "Sketch1" blind -2.45 (= "-( plate_thick / 2 ) + wall_clearance") named "d296_4" from offset 5 (= "plate_thick") named "d295_4"
position "Position16"
sketch "Sketch2" plane through (0, 0, 10) normal (0, 0, 1) x axis (-1, 0, 0)
  line L1 (-46.1449, 57.9621) -> (-21.0144, 57.9621)
  line L2 (-41.1449, 60.9621) -> (-46.1449, 57.9621)
  line L3 (-70.7839, 60.9621) -> (-41.1449, 60.9621)
  line L4 (-65.7839, 57.9621) -> (-70.7839, 60.9621)
  line L5 (-90.9144, 57.9621) -> (-65.7839, 57.9621)
  line L6 (-90.9144, 12.8316) -> (-90.9144, 57.9621)
  line L7 (-93.9144, 17.8316) -> (-90.9144, 12.8316)
  line L8 (-93.9144, -11.8074) -> (-93.9144, 17.8316)
  line L9 (-90.9144, -6.8074) -> (-93.9144, -11.8074)
  line L10 (-90.9144, -51.9379) -> (-90.9144, -6.8074)
  line L11 (-65.7839, -51.9379) -> (-90.9144, -51.9379)
  line L12 (-70.7839, -54.9379) -> (-65.7839, -51.9379)
  line L13 (-41.1449, -54.9379) -> (-70.7839, -54.9379)
  line L14 (-46.1449, -51.9379) -> (-41.1449, -54.9379)
  line L15 (-21.0144, -51.9379) -> (-46.1449, -51.9379)
  line L16 (-21.0144, -6.8074) -> (-21.0144, -51.9379)
  line L17 (-18.0144, -11.8074) -> (-21.0144, -6.8074)
  line L18 (-18.0144, 17.8316) -> (-18.0144, -11.8074)
  line L19 (-21.0144, 12.8316) -> (-18.0144, 17.8316)
  line L20 (-21.0144, 57.9621) -> (-21.0144, 12.8316)
  line L21 (-31.0144, 47.9621) -> (-80.9144, 47.9621)
  line L22 (-31.0144, -41.9379) -> (-31.0144, 47.9621)
  line L23 (-80.9144, -41.9379) -> (-31.0144, -41.9379)
  line L24 (-80.9144, 47.9621) -> (-80.9144, -41.9379)
  line L25 (-72.4644, 17.9621) -> (-39.4644, 17.9621)
  line L26 (-72.4644, 42.9621) -> (-72.4644, 17.9621)
  line L27 (-39.4644, 42.9621) -> (-72.4644, 42.9621)
  line L28 (-39.4644, 17.9621) -> (-39.4644, 42.9621)
  line L29 (-31.0144, 47.9621) -> (-80.9144, 47.9621)
  line L30 (-31.0144, -41.9379) -> (-31.0144, 47.9621)
  line L31 (-80.9144, -41.9379) -> (-31.0144, -41.9379)
  line L32 (-80.9144, 47.9621) -> (-80.9144, -41.9379)
  line L33 (-72.2144, -36.9379) -> (-39.7144, -36.9379)
  line L34 (-72.2144, -20.4379) -> (-72.2144, -36.9379)
  line L35 (-39.7144, -20.4379) -> (-72.2144, -20.4379)
  line L36 (-39.7144, -36.9379) -> (-39.7144, -20.4379)
  line L37 (-44.7144, -36.9379) -> (-39.7144, -36.9379)
  line L38 (-44.7144, -32.4379) -> (-44.7144, -36.9379)
  line L39 (-39.7144, -32.4379) -> (-44.7144, -32.4379)
  line L40 (-39.7144, -36.9379) -> (-39.7144, -32.4379)
  line L41 (-44.7144, -20.4379) -> (-39.7144, -20.4379)
  line L42 (-44.7144, -24.9379) -> (-44.7144, -20.4379)
  line L43 (-39.7144, -24.9379) -> (-44.7144, -24.9379)
  line L44 (-39.7144, -20.4379) -> (-39.7144, -24.9379)
  line L45 (-64.7144, -36.9379) -> (-54.7144, -36.9379)
  line L46 (-64.7144, -20.4379) -> (-64.7144, -36.9379)
  line L47 (-54.7144, -20.4379) -> (-64.7144, -20.4379)
  line L48 (-54.7144, -36.9379) -> (-54.7144, -20.4379)
  line L49 (-44.4644, 17.9621) -> (-39.4644, 17.9621)
  line L50 (-44.4644, 22.9621) -> (-44.4644, 17.9621)
  line L51 (-39.4644, 22.9621) -> (-44.4644, 22.9621)
  line L52 (-39.4644, 17.9621) -> (-39.4644, 22.9621)
  line L53 (-72.4644, 17.9621) -> (-67.4644, 17.9621)
  line L54 (-72.4644, 22.9621) -> (-72.4644, 17.9621)
  line L55 (-67.4644, 22.9621) -> (-72.4644, 22.9621)
  line L56 (-67.4644, 17.9621) -> (-67.4644, 22.9621)
  line L57 (-44.4644, 37.9621) -> (-39.4644, 37.9621)
  line L58 (-44.4644, 42.9621) -> (-44.4644, 37.9621)
  line L59 (-39.4644, 42.9621) -> (-44.4644, 42.9621)
  line L60 (-39.4644, 37.9621) -> (-39.4644, 42.9621)
  line L61 (-72.4644, 37.9621) -> (-67.4644, 37.9621)
  line L62 (-72.4644, 42.9621) -> (-72.4644, 37.9621)
  line L63 (-67.4644, 42.9621) -> (-72.4644, 42.9621)
  line L64 (-67.4644, 37.9621) -> (-67.4644, 42.9621)
  circle C1 centre (-41.7144, -34.9379) radius 1.2
  circle C2 centre (-41.7144, -22.4379) radius 1.2
  circle C3 centre (-41.9644, 20.4621) radius 1.7
  circle C4 centre (-69.9644, 20.4621) radius 1.7
  circle C5 centre (-41.9644, 40.4621) radius 1.7
  circle C6 centre (-69.9644, 40.4621) radius 1.7
  point P46 (-54.7144, -36.9379)
  point P26 (-39.4644, 17.9621)
  point P27 (-72.4644, 17.9621)
  point P29 (-39.4644, 42.9621)
  point P34 (-39.7144, -36.9379)
  point P35 (-72.2144, -36.9379)
  point P37 (-39.7144, -20.4379)
  point P38 (-44.7144, -36.9379)
  point P40 (-39.7144, -32.4379)
  point P41 (-44.7144, -20.4379)
  point P43 (-39.7144, -24.9379)
  point P44 (-41.7144, -34.9379)
  point P45 (-41.7144, -22.4379)
  point P47 (-64.7144, -36.9379)
  point P50 (-44.4644, 17.9621)
  point P52 (-39.4644, 22.9621)
  point P53 (-41.9644, 20.4621)
  horizontal L25
  vertical L26
  horizontal L27
  vertical L28
  horizontal L33
  vertical L34
  horizontal L35
  vertical L36
  horizontal L37
  vertical L38
  horizontal L39
  vertical L40
  horizontal L41
  vertical L42
  horizontal L43
  vertical L44
  horizontal L45
  vertical L46
  horizontal L47
  vertical L48
  coincident L33 P46
  horizontal L49
  vertical L50
  horizontal L51
  vertical L52
  dimension "d457" distance P26 P27 = 33 (= "fan_relay_board_width")
  dimension "d458" distance P26 P29 = 25 (= "fan_relay_board_height")
  dimension "d459" distance L26 L32 = 8.45 (= "( 49.90 mm - fan_relay_board_width ) / 2")
  dimension "d460" distance L27 L29 = 5
  dimension "d461" distance P34 P35 = 32.5 (= "mosfet_board_width")
  dimension "d462" distance P34 P37 = 16.5 (= "mosfet_baord_height")
  dimension "d463" distance L31 L33 = 5
  dimension "d464" distance L32 L34 = 8.7 (= "( 49.90 mm - mosfet_board_width ) / 2")
  dimension "d465" distance P34 P38 = 5
  dimension "d466" distance P34 P40 = 4.5
  dimension "d467" distance P37 P41 = 5
  dimension "d468" distance P37 P43 = 4.5
  dimension "M2_d" diameter C1 = 2.4
  dimension "d470" distance L33 P44 = 2
  dimension "d471" distance L40 P44 = 2
  dimension "d472" diameter C2 = 2.4 (= "M2_d")
  dimension "d473" distance L35 P45 = 2
  dimension "d474" distance L36 P45 = 2
  dimension "d475" distance P46 P47 = 10
  dimension "d476" distance L36 L48 = 15
  dimension "d477" distance P26 P50 = 5
  dimension "d478" distance P26 P52 = 5
  dimension "d479" diameter C3 = 3.4 (= "M3_d")
  dimension "d480" distance L25 P53 = 2.5
  dimension "d481" distance L28 P53 = 2.5
  dimension "d484" R-Pattern1-uDistance = -28 (= "-fan_relay_board_width + 5 mm")
  dimension "d485" R-Pattern1-vDistance = 20 (= "fan_relay_board_height - 5 mm")
  dimension "d488" R-Pattern2-uDistance = -28 (= "-fan_relay_board_width + 5 mm")
  dimension "d489" R-Pattern2-vDistance = 20 (= "fan_relay_board_height - 5 mm")
sketch "Sketch3" plane through (0, 0, 10) normal (0, 0, 1) x axis (-1, 0, 0)
  line L1 (-31.0144, -41.9379) -> (-31.0144, 47.9621)
  line L2 (-80.9144, -41.9379) -> (-31.0144, -41.9379)
  line L3 (-80.9144, 47.9621) -> (-80.9144, -41.9379)
  line L4 (-31.0144, 47.9621) -> (-80.9144, 47.9621)
  line L5 (-80.9144, -38.9379) -> (-31.0144, -38.9379)
  line L6 (-80.9144, -30.9379) -> (-80.9144, -38.9379)
  line L7 (-31.0144, -30.9379) -> (-80.9144, -30.9379)
  line L8 (-31.0144, -38.9379) -> (-31.0144, -30.9379)
  line L9 (-72.2144, -36.9379) -> (-39.7144, -36.9379)
  line L10 (-72.2144, -20.4379) -> (-72.2144, -36.9379)
  line L11 (-39.7144, -20.4379) -> (-72.2144, -20.4379)
  line L12 (-39.7144, -36.9379) -> (-39.7144, -20.4379)
  line L13 (-72.4644, 42.9621) -> (-72.4644, 17.9621)
  line L14 (-39.4644, 42.9621) -> (-72.4644, 42.9621)
  line L15 (-39.4644, 17.9621) -> (-39.4644, 42.9621)
  line L16 (-72.4644, 17.9621) -> (-39.4644, 17.9621)
  line L17 (-31.0144, -10.4379) -> (-80.9144, -10.4379)
  line L18 (-31.0144, -26.4379) -> (-31.0144, -10.4379)
  line L19 (-80.9144, -26.4379) -> (-31.0144, -26.4379)
  line L20 (-80.9144, -10.4379) -> (-80.9144, -26.4379)
  line L21 (-80.9144, 8.4621) -> (-31.0144, 8.4621)
  line L22 (-80.9144, 24.4621) -> (-80.9144, 8.4621)
  line L23 (-31.0144, 24.4621) -> (-80.9144, 24.4621)
  line L24 (-31.0144, 8.4621) -> (-31.0144, 24.4621)
  line L25 (-80.9144, 36.4621) -> (-31.0144, 36.4621)
  line L26 (-80.9144, 44.4621) -> (-80.9144, 36.4621)
  line L27 (-31.0144, 44.4621) -> (-80.9144, 44.4621)
  line L28 (-31.0144, 36.4621) -> (-31.0144, 44.4621)
  point P6 (-31.0144, -38.9379)
  point P9 (-31.0144, -30.9379)
  point P18 (-41.7144, -34.9379)
  point P21 (-31.0144, -26.4379)
  point P22 (-31.0144, -10.4379)
  point P23 (-41.7144, -22.4379)
  point P26 (-31.0144, 24.4621)
  point P27 (-31.0144, 8.4621)
  point P28 (-41.9644, 20.4621)
  point P31 (-31.0144, 36.4621)
  point P32 (-31.0144, 44.4621)
  point P33 (-41.9644, 40.4621)
  horizontal L5
  vertical L6
  horizontal L7
  vertical L8
  coincident L1 P6
  horizontal L19
  vertical L20
  horizontal L17
  vertical L18
  horizontal L21
  vertical L22
  horizontal L23
  vertical L24
  horizontal L25
  vertical L26
  horizontal L27
  vertical L28
  dimension "d490" distance P6 P9 = 8
  dimension "d491" distance L5 P18 = 4
  dimension "d492" distance P21 P22 = 16
  dimension "d494" distance L19 P23 = 4
  dimension "d495" distance P26 P27 = 16
  dimension "d496" distance L23 P28 = 4
  dimension "d497" distance P31 P32 = 8
  dimension "d498" distance L27 P33 = 4
extrude "Extrude3" add sketch "Sketch3" profile of L1 L3 L5 L6 L7 L8 L9 L10 L11 L12 L13 L14 L15 L16 L17 L18 L19 L20 L21 L22 L23 L24 L25 L26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 no distance stored
extrude "Extrude4" add sketch "Sketch2" profile of L25 L26 L27 L28 L33 L35 L36 L37 L38 L39 L40 L41 L42 L43 L44 C1 C2 L45 L46 L47 L48 L49 L50 L51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 along normal blind 5 (= "el_stand_height")
sketch "Sketch4" plane through (0, 0, 15) normal (0, 0, 1) x axis (-1, 0, 0)
  line L1 (-44.4644, 22.9621) -> (-39.4644, 22.9621)
  line L2 (-44.4644, 17.9621) -> (-44.4644, 22.9621)
  line L3 (-39.4644, 17.9621) -> (-44.4644, 17.9621)
  line L4 (-39.4644, 22.9621) -> (-39.4644, 17.9621)
  circle C1 centre (-69.9644, 20.4621) radius 1.7
  circle C2 centre (-41.9644, 20.4621) radius 1.7
  circle C3 centre (-41.9644, 40.4621) radius 1.7
  circle C4 centre (-69.9644, 40.4621) radius 1.7
  circle C5 centre (-41.7144, -22.4379) radius 1.2
  circle C6 centre (-41.7144, -34.9379) radius 1.2
hole "Hole1" HoleDepth 7.5 (= "el_stand_height + ( plate_thick * 0.5 )") HoleDiameter 2.4 TipAngle 118
hole "Hole2" HoleDepth 7.5 (= "el_stand_height + ( plate_thick * 0.5 )") HoleDiameter 3.4 TipAngle 118
sketch "Sketch5" plane through (0, 0, 10) normal (0, 0, 1) x axis (-1, 0, 0)
  line L1 (-64.7144, -30.9379) -> (-64.7144, -36.9379)
  line L2 (-80.9144, -30.9379) -> (-64.7144, -30.9379)
  line L3 (-80.9144, -26.4379) -> (-80.9144, -30.9379)
  line L4 (-64.7144, -26.4379) -> (-80.9144, -26.4379)
  line L5 (-64.7144, -20.4379) -> (-64.7144, -26.4379)
  line L6 (-54.7144, -20.4379) -> (-64.7144, -20.4379)
  line L7 (-54.7144, -26.4379) -> (-54.7144, -20.4379)
  line L8 (-31.0144, -26.4379) -> (-54.7144, -26.4379)
  line L9 (-31.0144, -30.9379) -> (-31.0144, -26.4379)
  line L10 (-54.7144, -30.9379) -> (-31.0144, -30.9379)
  line L11 (-54.7144, -36.9379) -> (-54.7144, -30.9379)
  line L12 (-64.7144, -36.9379) -> (-54.7144, -36.9379)
  line L13 (-67.4644, 17.9621) -> (-67.4644, 22.9621)
  line L14 (-72.4644, 17.9621) -> (-67.4644, 17.9621)
  line L15 (-72.4644, 22.9621) -> (-72.4644, 17.9621)
  line L16 (-67.4644, 22.9621) -> (-72.4644, 22.9621)
  line L17 (-39.4644, 17.9621) -> (-39.4644, 22.9621)
  line L18 (-44.4644, 17.9621) -> (-39.4644, 17.9621)
  line L19 (-44.4644, 22.9621) -> (-44.4644, 17.9621)
  line L20 (-39.4644, 22.9621) -> (-44.4644, 22.9621)
  line L21 (-39.7144, -36.9379) -> (-39.7144, -32.4379)
  line L22 (-44.7144, -36.9379) -> (-39.7144, -36.9379)
  line L23 (-44.7144, -32.4379) -> (-44.7144, -36.9379)
  line L24 (-39.7144, -32.4379) -> (-44.7144, -32.4379)
  line L25 (-67.4644, 37.9621) -> (-67.4644, 42.9621)
  line L26 (-72.4644, 37.9621) -> (-67.4644, 37.9621)
  line L27 (-72.4644, 42.9621) -> (-72.4644, 37.9621)
  line L28 (-67.4644, 42.9621) -> (-72.4644, 42.9621)
  line L29 (-39.4644, 37.9621) -> (-39.4644, 42.9621)
  line L30 (-44.4644, 37.9621) -> (-39.4644, 37.9621)
  line L31 (-44.4644, 42.9621) -> (-44.4644, 37.9621)
  line L32 (-39.4644, 42.9621) -> (-44.4644, 42.9621)
  line L33 (-44.7144, -24.9379) -> (-39.7144, -24.9379)
  line L34 (-44.7144, -20.4379) -> (-44.7144, -24.9379)
  line L35 (-39.7144, -20.4379) -> (-44.7144, -20.4379)
  line L36 (-39.7144, -24.9379) -> (-39.7144, -20.4379)
  line L37 (-80.9144, 47.9621) -> (-80.9144, 44.4621)
  line L38 (-31.0144, 47.9621) -> (-80.9144, 47.9621)
  line L39 (-31.0144, 44.4621) -> (-31.0144, 47.9621)
  line L40 (-80.9144, 44.4621) -> (-31.0144, 44.4621)
  line L41 (-31.0144, -38.9379) -> (-80.9144, -38.9379)
  line L42 (-31.0144, -41.9379) -> (-31.0144, -38.9379)
  line L43 (-80.9144, -41.9379) -> (-31.0144, -41.9379)
  line L44 (-80.9144, -38.9379) -> (-80.9144, -41.9379)
  line L45 (-31.0144, 36.4621) -> (-80.9144, 36.4621)
  line L46 (-31.0144, 24.4621) -> (-31.0144, 36.4621)
  line L47 (-80.9144, 24.4621) -> (-31.0144, 24.4621)
  line L48 (-80.9144, 36.4621) -> (-80.9144, 24.4621)
  line L49 (-46.1449, 57.9621) -> (-21.0144, 57.9621)
  line L50 (-41.1449, 60.9621) -> (-46.1449, 57.9621)
  line L51 (-70.7839, 60.9621) -> (-41.1449, 60.9621)
  line L52 (-65.7839, 57.9621) -> (-70.7839, 60.9621)
  line L53 (-90.9144, 57.9621) -> (-65.7839, 57.9621)
  line L54 (-90.9144, 12.8316) -> (-90.9144, 57.9621)
  line L55 (-93.9144, 17.8316) -> (-90.9144, 12.8316)
  line L56 (-93.9144, -11.8074) -> (-93.9144, 17.8316)
  line L57 (-90.9144, -6.8074) -> (-93.9144, -11.8074)
  line L58 (-90.9144, -51.9379) -> (-90.9144, -6.8074)
  line L59 (-65.7839, -51.9379) -> (-90.9144, -51.9379)
  line L60 (-70.7839, -54.9379) -> (-65.7839, -51.9379)
  line L61 (-41.1449, -54.9379) -> (-70.7839, -54.9379)
  line L62 (-46.1449, -51.9379) -> (-41.1449, -54.9379)
  line L63 (-21.0144, -51.9379) -> (-46.1449, -51.9379)
  line L64 (-21.0144, -6.8074) -> (-21.0144, -51.9379)
  line L65 (-18.0144, -11.8074) -> (-21.0144, -6.8074)
  line L66 (-18.0144, 17.8316) -> (-18.0144, -11.8074)
  line L67 (-21.0144, 12.8316) -> (-18.0144, 17.8316)
  line L68 (-21.0144, 57.9621) -> (-21.0144, 12.8316)
  line L69 (-80.9144, -10.4379) -> (-31.0144, -10.4379)
  line L70 (-80.9144, 8.4621) -> (-80.9144, -10.4379)
  line L71 (-31.0144, 8.4621) -> (-80.9144, 8.4621)
  line L72 (-31.0144, -10.4379) -> (-31.0144, 8.4621)
  curve K1
  curve K2
  curve K3
  curve K4
  line L73 (-55.9644, 20.0621) -> (-55.9644, -129.9379)
  curve K5
  curve K6
  curve K7
  curve K8
  perpendicular L51 L73
  midpoint L61 L73
  coincident L73
  coincident L73
  dimension "d509" Text1-Height = 5
  dimension "d511" Text2-Height = 5
emboss "Emboss1" sketch "Sketch5" Depth 1 (= "text_emboss") Horizontal Distance 0 Vertical Distance 0 Rotation Angle 0
sketch "Sketch4" plane through (0, 61.9879, 0) normal (0, 1, 0) x axis (1, 0, 0)
  line L1 (11.0351, -5.05) -> (100.8937, -5.05)
  line L2 (11.0351, -74.95) -> (11.0351, -5.05)
  line L3 (100.8937, -74.95) -> (11.0351, -74.95)
  line L4 (100.8937, -5.05) -> (100.8937, -74.95)
  line L5 (36.6374, -5.05) -> (36.6374, -12.415)
  line L6 (26.6374, -5.05) -> (26.6374, -12.415)
  circle C1 centre (15.9644, -20) radius 1.7
  circle C2 centre (95.9644, -60) radius 1.7
  circle C3 centre (95.9644, -20) radius 1.7
  circle C4 centre (15.9644, -60) radius 1.7
  arc A1 centre (31.6374, -12.415) radius 5 clockwise from (36.6374, -12.415) to (26.6374, -12.415)
  point P12 (36.6374, -5.05)
  point P14 (26.6374, -5.05)
  coincident L1 P12
  tangent L5 A1
  coincident L1 P14
  tangent L6 A1
  perpendicular L1 L6
  dimension "cable_hole_d" diameter A1 = 10
extrude "Extrude4" cut sketch "Sketch4" profile of A1 L1 L5 L6 against normal blind 2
